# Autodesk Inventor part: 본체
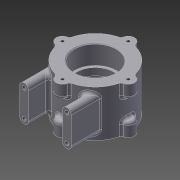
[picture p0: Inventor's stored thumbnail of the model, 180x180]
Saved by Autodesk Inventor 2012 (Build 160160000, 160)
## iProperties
Created: 2015-03
Part Number: 본체
Material: 알루미늄-6061
Document SubType Name: Modeling
Designer: Administrator
Density: 2.71 g/cm^3
Mass: 450.306 g
Surface Area: 333.505 cm^2
Volume: 166.165 cm^3
Author: Administrator
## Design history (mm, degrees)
sketch "스케치1"
  geometry: C1 r 37 at (0, 0); 1 further point
  constraints: 1 centre point, 1 coincident
  dimensions: "d0" = 74 diameter of C1
extrude "돌출1" new body sketch "스케치1" distance "d1" = 52; taper "d2" = 0 deg
sketch "스케치2"
  geometry: C1 r 37 at (0, 0) reference; C2 r 23.5 at (0, 0)
  constraints: 1 centre point, 1 coincident
  dimensions: "d3" = 47 diameter of C2
extrude "돌출2" cut sketch "스케치2" distance "d4" = 22; taper "d5" = 0 deg
sketch "스케치3"
  geometry: C1 r 23.5 at (0, 0) reference; C2 r 21 at (0, 0)
  constraints: 1 centre point, 1 coincident
  dimensions: "d6" = 42 diameter of C2
extrude "돌출3" cut sketch "스케치3" distance "d7" = 8; taper "d8" = 0 deg
sketch "스케치4"
  geometry: C1 r 37 at (0, 0) reference; C2 r 23.5 at (0, 0)
  constraints: 1 centre point, 1 coincident
  dimensions: "d9" = 47 diameter of C2
extrude "돌출4" cut sketch "스케치4" distance "d10" = 22; taper "d11" = 0 deg
sketch "스케치5"
  geometry: C1 r 7 at (0, 37); C2 r 7 at (-37, 0); C3 r 7 at (0, -37); C4 r 7 at (37, 0); A1 r 37 centre (0, 0) between (0, 37) and (-37, 0) reference
  constraints: 4 centre point, 4 point on circle
  dimensions: "d13" = 14 diameter of C1; "d14" = 14 diameter of C2; "d15" = 14 diameter of C3; "d16" = 14 diameter of C4
extrude "돌출5" join sketch "스케치5" distance "d17" = 15; taper "d18" = 0 deg
sketch "스케치6"
  geometry: C1 r 7 at (0, 37); C2 r 7 at (-37, 0); C3 r 7 at (0, -37); C4 r 7 at (37, 0); A1 r 37 centre (0, 0) between (0, 37) and (-37, 0) reference
  constraints: 4 centre point, 4 point on circle
  dimensions: "d19" = 14 diameter of C1; "d20" = 14 diameter of C2; "d21" = 14 diameter of C3; "d22" = 14 diameter of C4
extrude "돌출6" join sketch "스케치6" distance "d23" = 15; taper "d24" = 0 deg
sketch "스케치7"
  geometry: 4 further points
hole "구멍1" sketch "스케치7" at (0, 37), (-37, 0), (0, -37), (37, 0) diameter "d25" = 3.459; stored, may be unused: countersink angle "d29" = 90 deg, drill point angle "d31" = 118 deg; dims "d26" = 8, "d27" = 4, "d28" = 2, "d30" = 11
sketch "스케치8"
  geometry: A1 r 7 centre (-37, 0) between (-36.338, 6.969) and (-36.338, -6.969) reference; A2 r 7 centre (0, -37) between (-6.969, -36.338) and (6.969, -36.338) reference; A3 r 7 centre (37, 0) between (36.338, -6.969) and (36.338, 6.969) reference; A4 r 7 centre (0, 37) between (6.969, 36.338) and (-6.969, 36.338) reference; 4 further points
  constraints: 4 coincident
hole "구멍2" sketch "스케치8" at (0, 37), (-37, 0), (0, -37), (37, 0) diameter "d32" = 3.459; stored, may be unused: countersink angle "d36" = 90 deg, drill point angle "d38" = 118 deg; dims "d33" = 8, "d34" = 4, "d35" = 2, "d37" = 11
node "작업 평면1"
sketch "스케치9"
  geometry: L1 (-19, 41)-(-19, 11); L2 (-29, 41)-(-29, 11); L3 (19, 41)-(19, 11); L4 (29, 41)-(29, 11); A1 r 5 centre (-24, 41) between (-19, 41) and (-29, 41); A2 r 5 centre (-24, 11) between (-29, 11) and (-19, 11); A3 r 5 centre (24, 41) between (29, 41) and (19, 41); A4 r 5 centre (24, 11) between (19, 11) and (29, 11); 1 further point
  constraints: 8 end point, 8 point on circle, 4 centre point, 2 tangent
extrude "돌출7" join sketch "스케치9" distance "d48" = 35; taper "d49" = 0 deg
sketch "스케치10"
  geometry: A1 r 5 centre (-24, 41) between (-19, 41) and (-29, 41) reference; A2 r 5 centre (-24, 11) between (-29, 11) and (-19, 11) reference; 3 further points
  constraints: 2 coincident
hole "구멍3" sketch "스케치10" at (-24, 41), (-24, 11) diameter "d50" = 4.459; stored, may be unused: countersink angle "d54" = 90 deg, drill point angle "d56" = 118 deg; dims "d51" = 6, "d52" = 4, "d53" = 2, "d55" = 8
sketch "스케치11"
  geometry: A1 r 5 centre (24, 41) between (29, 41) and (19, 41) reference; A2 r 5 centre (24, 11) between (19, 11) and (29, 11) reference; 3 further points
  constraints: 2 coincident
hole "구멍4" sketch "스케치11" at (24, 41), (24, 11) diameter "d57" = 4.459; stored, may be unused: countersink angle "d61" = 90 deg, drill point angle "d63" = 118 deg; dims "d58" = 6, "d59" = 4, "d60" = 2, "d62" = 8
node "작업 평면2"
sketch "스케치12"
  geometry: L1 (0, 0)-(-26.517, 26.517)
  constraints: 2 end point
node "작업 평면3"
sketch "스케치13"
  geometry: L1 (-3.002, -20.739)-(-3.002, 20.74); L2 (-3.002, 20.74)-(3.002, 20.74); L3 (3.002, 20.74)-(3.002, -20.739); L4 (3.002, -20.739)-(-3.002, -20.739); 1 further point
  constraints: 2 other
feature "엠보싱1" sketch "스케치13" dims "d11" = 0, "d70" = 0.5, "d71" = 0
fillet "모깎기1" dims "d72" = 3
fillet "모깎기2" dims "d73" = 3
fillet "모깎기3" dims "d74" = 3
fillet "모깎기4" dims "d75" = 3
fillet "모깎기5" dims "d76" = 3
fillet "모깎기6" dims "d77" = 3
chamfer "모따기1" distance "d78" = 1; stored, may be unused: second distance "d79" = 2, angle "d80" = 45 deg
fillet "모깎기7" dims "d84" = 0.3
node "솔리드1"
other parameters: "d39" = -56, "d64" = 26
